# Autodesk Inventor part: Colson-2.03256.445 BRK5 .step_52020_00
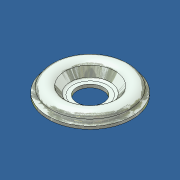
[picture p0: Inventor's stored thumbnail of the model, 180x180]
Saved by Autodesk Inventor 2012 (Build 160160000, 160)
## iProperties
Created: 2010-10
Part Number: Colson-2.03256.445 BRK5 .step_52020_00
Document SubType Name: Modeling
Designer: Administrator
Density: 7.85 g/cm^3
Material: Steel
Mass: 74.8965 g
Surface Area: 78.9657 cm^2
Volume: 9.54096 cm^3
Author: Administrator
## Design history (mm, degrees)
feature "Base1"
body "Solid1"
